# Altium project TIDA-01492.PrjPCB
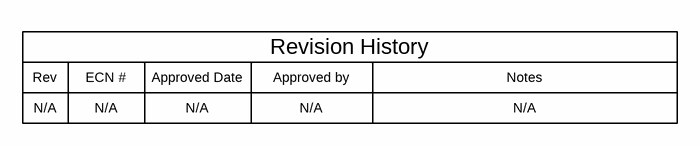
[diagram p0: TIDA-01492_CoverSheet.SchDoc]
CopyrightYear: 2017; EVM_Orderable: N/A; PCB_Layout: Luis Cordova; PCB_Rev: E1; PRJ_Customer: Public Release; PRJ_Engineer: Luis Cordova; PRJ_Number: TIDA-01492; PRJ_Title: Integrated Power Front End and Multi-Phase Processor Supply Reference Design; SCH_Rev: E1; TechSupport: http://www.ti.com/support; TID: TIDA-01492
5 sheets, 142 parts. Net scope: flat (ports and power ports of the same name join across sheets).
Board file: TIDA-01492 Board.PcbDoc
Sheets:
  TIDA-01492_CoverSheet.SchDoc
  Main Supply + Smart Diode.SchDoc
  Core-Voltage Supply.SchDoc
  Memory + IO + CAN Supply.SchDoc
  TIDA-01492_EVM_Hardware.SchDoc

## Sheet TIDA-01492_CoverSheet.SchDoc
size 431 x 279 mm; Date: Not shown in title block; ApprovedBy: Not shown in title block; CheckedBy: Not shown in title block; Author: Not shown in title block; CompanyName: Not shown in title block; Engineer: Not shown in title block; Organization: Not shown in title block; Address1: Not shown in title block; Address2: Not shown in title block; Address3: Not shown in title block; Address4: Not shown in title block; DocumentNumber: 1; Revision: Use project parameter SCH_Rev; SheetNumber: 1; SheetTotal: 5; PageSetup: Record=PageOptions¦CenterHorizontal=True¦CenterVertical=True¦PrintScale=1.00¦XCorrection=1.00¦YCorrection=1.00¦PrintKind=0¦BorderSize=5000000¦LeftOffset=0¦BottomOffset=0¦Orientation=2¦PaperLength=1000¦PaperWidth=1000¦Scale=100¦PaperSource=15¦PrintQuality=600¦MediaType=1¦DitherType=10¦PaperKind=Letter¦PrintScaleMode=1

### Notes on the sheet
- Rev
- N/A
- ECN #
- Approved Date
- Approved by
- Revision History
- Notes

## Sheet Main Supply + Smart Diode.SchDoc
size 431 x 279 mm; Date: Not shown in title block; ApprovedBy: Not shown in title block; CheckedBy: Not shown in title block; Author: Not shown in title block; CompanyName: Not shown in title block; Engineer: Not shown in title block; Organization: Not shown in title block; Address1: Not shown in title block; Address2: Not shown in title block; Address3: Not shown in title block; Address4: Not shown in title block; DocumentNumber: 1; Revision: Use project parameter SCH_Rev; SheetNumber: 2; SheetTotal: 5; PageSetup: Record=PageOptions¦CenterHorizontal=True¦CenterVertical=True¦PrintScale=1.00¦XCorrection=1.00¦YCorrection=1.00¦PrintKind=0¦BorderSize=5000000¦LeftOffset=0¦BottomOffset=0¦Orientation=2¦PaperLength=1000¦PaperWidth=1000¦Scale=100¦PaperSource=15¦PrintQuality=600¦MediaType=1¦DitherType=10¦PaperKind=Letter¦PrintScaleMode=1
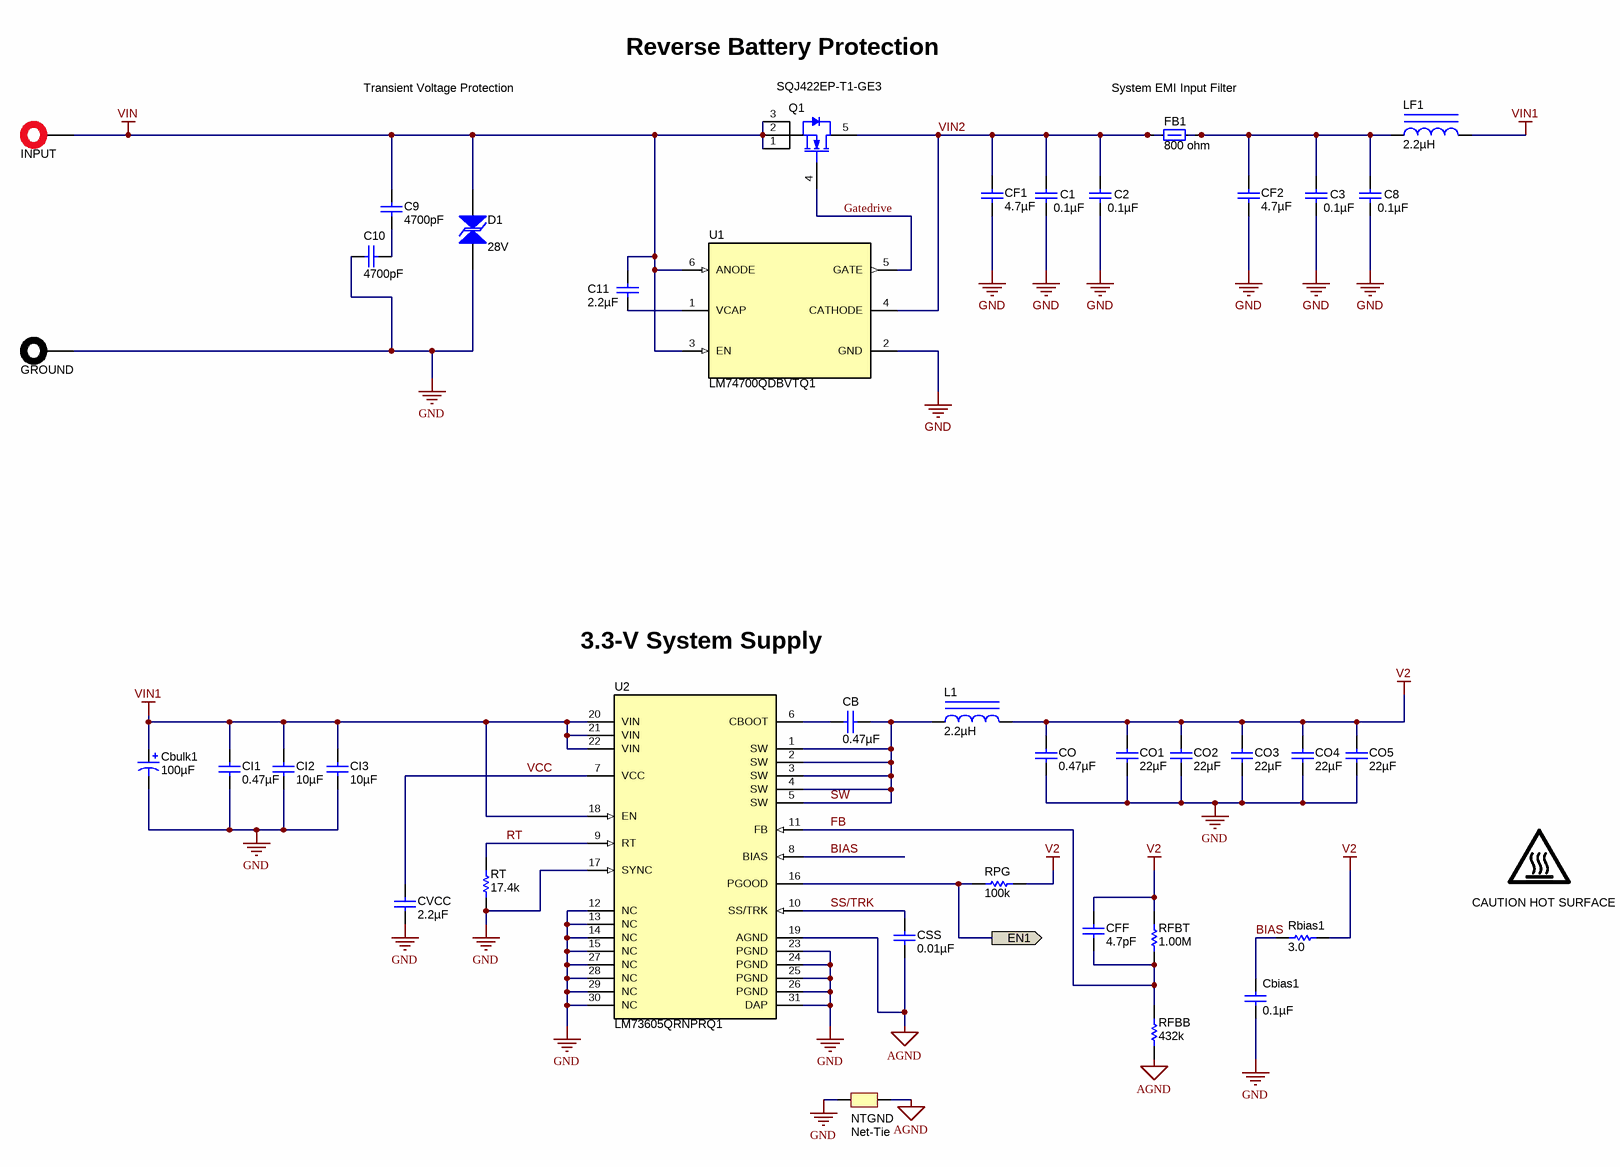
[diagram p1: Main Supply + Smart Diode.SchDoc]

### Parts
C1  ValueDisplayed: 0.1µF  [0603S]  (hidden comment: GCM188R71C104KA37J)
C2  ValueDisplayed: 0.1µF  [0603S]  (hidden comment: GCM188R71C104KA37J)
C3  ValueDisplayed: 0.1µF  [0603S]  (hidden comment: GCM188R71C104KA37J)
C8  ValueDisplayed: 0.1µF  [0603S]  (hidden comment: GCM188R71C104KA37J)
C9  ValueDisplayed: 4700pF  [0603]  (hidden comment: C0603C472J1GAC7867)
C10  ValueDisplayed: 4700pF  [0603]  (hidden comment: C0603C472J1GAC7867)
C11  ValueDisplayed: 2.2µF  [0805_HV]  (hidden comment: C2012X5R1H225K125AB)
CB  ValueDisplayed: 0.47µF  [0603L]  (hidden comment: GRM188R61E474KA12D)
Cbias1  ValueDisplayed: 0.1µF  [0603S]  (hidden comment: GCM188R71C104KA37J)
Cbulk1  ValueDisplayed: 100µF  [HXB_JA0]  (hidden comment: HHXB500ARA101MJA0G)
CF1  ValueDisplayed: 4.7µF  [1210_280]  (hidden comment: CGA6P3X7R1H475M250AB)
CF2  ValueDisplayed: 4.7µF  [1210_280]  (hidden comment: CGA6P3X7R1H475M250AB)
CFF  ValueDisplayed: 4.7pF  [0603]  (hidden comment: 06035A4R7CAT2A)
CI1  ValueDisplayed: 0.47µF  [0603]  (hidden comment: GRM21BR71H474KA88L)
CI2  ValueDisplayed: 10µF  [1210_270]  (hidden comment: GRM32ER71H106KA12L)
CI3  ValueDisplayed: 10µF  [1210_270]  (hidden comment: GRM32ER71H106KA12L)
CO  ValueDisplayed: 0.47µF  [0805_HV]  (hidden comment: GRM21BR71H474KA88L)
CO1  ValueDisplayed: 22µF  [1210_270]  (hidden comment: GRM32ER71C226KE18L)
CO2  ValueDisplayed: 22µF  [1210_270]  (hidden comment: GRM32ER71C226KE18L)
CO3  ValueDisplayed: 22µF  [1210_270]  (hidden comment: GRM32ER71C226KE18L)
CO4  ValueDisplayed: 22µF  [1210_270]  (hidden comment: GRM32ER71C226KE18L)
CO5  ValueDisplayed: 22µF  [1210_270]  (hidden comment: GRM32ER71C226KE18L)
CSS  ValueDisplayed: 0.01µF  [0603]  (hidden comment: 06031C103MAT2A)
CVCC  ValueDisplayed: 2.2µF  [0603]  (hidden comment: GRM188C81A225KE34D)
D1  value 28V  [SMB-Bi]  (hidden comment: SMBJ28CA-13-F)
FB1  ValueDisplayed: 800 ohm  [2220_390]  (hidden comment: HR2220V801R-10)
GND_  GROUND  [6092]
IN  INPUT  [6091]
L1  ValueDisplayed: 2.2µH  [XAL7030]  (hidden comment: XAL7030-222MEB)
LF1  ValueDisplayed: 2.2µH  [XAL5030]  (hidden comment: XAL5030-222MEB)
LOGO4  CAUTION HOT SURFACE  [IEC_HotSurface_Small]  (no BOM)
NTGND  Net-Tie  [Net-Tie_20milWide_60milLong]  (net tie, no BOM)
Q1  SQJ422EP-T1-GE3  [PowerPAK_SO-8L]
Rbias1  ValueDisplayed: 3.0  [0402S]  (hidden comment: CRCW04023R00JNED)
RFBB  ValueDisplayed: 432k  [0603]  (hidden comment: CRCW0603432KFKEA)
RFBT  ValueDisplayed: 1.00M  [0603]  (hidden comment: CRCW06031M00FKEA)
RPG  ValueDisplayed: 100k  [0603]  (hidden comment: CRCW0603100KFKEA)
RT  ValueDisplayed: 17.4k  [0603]  (hidden comment: CRCW060317K4FKEA)
U1  LM74700QDBVTQ1  [DDC0006A_N]
U2  LM73605QRNPRQ1  [RNP0030A]

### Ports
EN1 (out)

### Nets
AGND: CSS.2 NTGND.2 RFBB.1 U2.19(AGND)
GND: C1.2 C2.2 C3.2 C8.2 C10.1 Cbias1.2 Cbulk1.2(-) CF1.2 CF2.2 CI1.1 CI2.1 CI3.1 CO.1 CO1.2 CO2.2 CO3.2 CO4.2 CO5.2 CVCC.2 D1.2 GND_.1 NTGND.1 RT.2 U1.2(GND) U2.12(NC) U2.13(NC) U2.14(NC) U2.15(NC) U2.17(SYNC) U2.23(PGND) U2.24(PGND) U2.25(PGND) U2.26(PGND) U2.27(NC) U2.28(NC) U2.29(NC) U2.30(NC) U2.31(DAP)
V2: CFF.1 CO.2 CO1.1 CO2.1 CO3.1 CO4.1 CO5.1 L1.2 Rbias1.2 RFBT.2 RPG.2
VIN: C9.1 C11.1 D1.1 IN.1 Q1.1(S) Q1.2(S) Q1.3(S) U1.3(EN) U1.6(ANODE)
VIN1: Cbulk1.1(+) CI1.2 CI2.2 CI3.2 LF1.2 U2.18(EN) U2.20(VIN) U2.21(VIN) U2.22(VIN)
BIAS: Cbias1.1 Rbias1.1 U2.8(BIAS)
FB: CFF.2 RFBB.2 RFBT.1 U2.11(FB)
Gatedrive: Q1.4(G) U1.5(GATE)
RT: RT.1 U2.9(RT)
SS/TRK: CSS.1 U2.10(SS/TRK)
SW: CB.2 L1.1 U2.1(SW) U2.2(SW) U2.3(SW) U2.4(SW) U2.5(SW)
VCC: CVCC.1 U2.7(VCC)
VIN2: C1.1 C2.1 CF1.1 FB1.1 Q1.5(D) U1.4(CATHODE)
NetC3_1: C3.1 C8.1 CF2.1 FB1.2 LF1.1
NetC9_2: C9.2 C10.2
NetC11_2: C11.2 U1.1(VCAP)
NetCB_1: CB.1 U2.6(CBOOT)
NetRPG_1: RPG.1 U2.16(PGOOD) ; port EN1

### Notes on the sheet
- Reverse Battery Protection
- Transient Voltage Protection
- (near FB1) System EMI Input Filter
- 3.3-V System Supply

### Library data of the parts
C1-C3 C8 = GCM188R71C104KA37J: CAP, CERM, 0.1 µF, 16 V, +/- 10%, X7R, AEC-Q200 Grade 1, 0603; Manufacturer: MuRata; Polarized: N; CompType: Capacitor; Value: 0.1uF; U/M: EA; Cap_F: 0.0000001; Tolerance_%: 10; Value1: Unknown; VDC_V: 16; Value2: 16V; TaMin_C: -55; TaMax_C: 125; Cap_Case: 0603; AEC Category: Q200; AEC Qualified: Y; AEC Grade: 1; SizeArea_mm2: 1.28; SizeAreaWB_mm2: 4.68; SizeX_mm: 1.6; SizeY_mm: 0.8
C9 C10 = C0603C472J1GAC7867: CAP, CERM, 4700 pF, 100 V, +/- 5%, C0G/NP0, 0603; Manufacturer: Kemet; Polarized: N; CompType: Capacitor; Value: 4700pF; U/M: EA; Cap_F: 0.0000000047; Tolerance_%: 5; Value1: Unknown; VDC_V: 100; Value2: 100V; TaMin_C: -55; TaMax_C: 125; SizeArea_mm2: 1.28; SizeAreaWB_mm2: 4.68; SizeX_mm: 1.6; SizeY_mm: 0.8; SizeZ_mm: 1; AEC Category: Q200
C11 = C2012X5R1H225K125AB: CAP, CERM, 2.2 µF, 50 V, +/- 10%, X5R, 0805; Manufacturer: TDK; CompType: Capacitor; Value: 2.2uF; Polarized: N; U/M: EA; Cap_F: 0.0000022; Tolerance_%: 10; Value1: Unknown; VDC_V: 50; Value2: 50V; TaMin_C: -55; TaMax_C: 85; Cap_Case: 0805
CB = GRM188R61E474KA12D: CAP, CERM, 0.47uF, 25V, +/-10%, X5R, 0603; Manufacturer: MuRata; Polarized: N; CompType: Capacitor; U/M: EA; Cap_F: 0.00000047; Tolerance_%: 10; Value1: Unknown; VDC_V: 25; TaMin_C: -55; TaMax_C: 85; Cap_Case: 0603
Cbias1 = GCM188R71C104KA37J: CAP, CERM, 0.1 µF, 16 V, +/- 10%, X7R, AEC-Q200 Grade 1, 0603; Manufacturer: MuRata; Polarized: N; CompType: Capacitor; Value: 0.1uF; U/M: EA; Cap_F: 0.0000001; Tolerance_%: 10; Value1: Unknown; VDC_V: 16; Value2: 16V; TaMin_C: -55; TaMax_C: 125; Cap_Case: 0603; AEC Category: Q200; AEC Qualified: Y; AEC Grade: 1
Cbulk1 = HHXB500ARA101MJA0G: CAP, Aluminum Polymer, 100 µF, 50 V, +/- 20%, 0.025 ohm, AEC-Q200 Grade 2, D10xL10mm SMD; Manufacturer: Chemi-Con; Polarized: Y; CompType: Capacitor; Value: 100uF; U/M: EA; Cap_F: 0.0001; Tolerance_%: 20; VDC_V: 50; Value2: 50V; ESR_ohm: 0.025; IRMS_A: 2; TaMin_C: -55; TaMax_C: 105; Cap_Case: 10x10mm; AEC Category: Q200
CF1 CF2 = CGA6P3X7R1H475M250AB: CAP, CERM, 4.7 µF, 50 V, +/- 20%, X7R, AEC-Q200 Grade 1, 1210; Manufacturer: TDK; Polarized: N; CompType: Capacitor; Value: 4.7uF; U/M: EA; Cap_F: 0.0000047; Tolerance_%: 20; Value1: Unknown; VDC_V: 50; Value2: 50V; TaMin_C: -55; TaMax_C: 125; Cap_Case: 1210; AEC Category: Q200; AEC Qualified: Y; AEC Grade: 1
CFF = 06035A4R7CAT2A: CAP, CERM, 4.7 pF, 50 V, +/- 5%, C0G/NP0, 0603; Manufacturer: AVX; Polarized: N; CompType: Capacitor; Value: 4.7pF; U/M: EA; Cap_F: 0.0000000000047; Tolerance_%: 5; ESR_ohm: 0.633; Value1: 0.633 ohm; VDC_V: 50; Value2: 50V; TaMin_C: -55; TaMax_C: 125; AEC Category: Q200
CI1 = GRM21BR71H474KA88L: CAP, CERM, 0.47 µF, 50 V, +/- 10%, X7R, 0805; Manufacturer: MuRata; Polarized: N; CompType: Capacitor; Value: 0.47uF; U/M: EA; Cap_F: 0.00000047; Tolerance_%: 10; Value1: Unknown; VDC_V: 50; Value2: 50V; TaMin_C: -55; TaMax_C: 125; Cap_Case: 0805; SizeArea_mm2: 2.5; SizeAreaWB_mm2: 6.75; SizeX_mm: 2; SizeY_mm: 1.25; SizeZ_mm: 1.45; AEC Category: Q200
CI2 CI3 = GRM32ER71H106KA12L: CAP, CERM, 10 µF, 50 V, +/- 10%, X7R, 1210; Manufacturer: MuRata; Polarized: N; CompType: Capacitor; Value: 10uF; U/M: EA; Cap_F: 0.00001; Tolerance_%: 10; Value1: Unknown; VDC_V: 50; Value2: 50V; TaMin_C: -55; TaMax_C: 125; Cap_Case: 1210; SizeArea_mm2: 8; SizeAreaWB_mm2: 14.7; SizeX_mm: 3.2; SizeY_mm: 2.5; SizeZ_mm: 2.7; AEC Category: Q200
CO = GRM21BR71H474KA88L: CAP, CERM, 0.47 µF, 50 V, +/- 10%, X7R, 0805; Manufacturer: MuRata; Polarized: N; CompType: Capacitor; Value: 0.47uF; U/M: EA; Cap_F: 0.00000047; Tolerance_%: 10; Value1: Unknown; VDC_V: 50; Value2: 50V; TaMin_C: -55; TaMax_C: 125; Cap_Case: 0805
CO1-CO5 = GRM32ER71C226KE18L: CAP, CERM, 22 µF, 16 V, +/- 10%, X7R, 1210; Manufacturer: MuRata; Polarized: N; CompType: Capacitor; Value: 22uF; U/M: EA; Cap_F: 0.000022; Tolerance_%: 10; ESR_ohm: 0.003; Value1: 0.003 ohm; VDC_V: 16; Value2: 16V; TaMin_C: -55; TaMax_C: 125; Cap_Case: 1210; AEC Category: Q200; SizeArea_mm2: 8; SizeAreaWB_mm2: 14.7; SizeX_mm: 3.2; SizeY_mm: 2.5; SizeZ_mm: 2.7
CSS = 06031C103MAT2A: CAP, CERM, 0.01 µF, 100 V, +/- 20%, X7R, 0603; Manufacturer: AVX; Polarized: N; CompType: Capacitor; Value: 0.01uF; U/M: EA; Cap_F: 0.00000001; Tolerance_%: 20; ESR_ohm: 0.098; Value1: 0.098 ohm; VDC_V: 100; Value2: 100V; TaMin_C: -55; TaMax_C: 125
CVCC = GRM188C81A225KE34D: CAP, CERM, 2.2uF, 10V, +/-10%, X6S, 0603; Manufacturer: MuRata; Polarized: N; CompType: Capacitor; U/M: EA; Cap_F: 0.0000022; Tolerance_%: 10; Value1: Unknown; TaMin_C: -55; TaMax_C: 105
D1 = SMBJ28CA-13-F: Diode, TVS, Bi, 28 V, 45.4 Vc, SMB; Manufacturer: Diodes Inc.; U/M: EA; Power_W: 5; Vr_V: 28; Value1: 5W; AEC Category: Q101; AEC Qualified: N
FB1 = HR2220V801R-10: Ferrite Bead, 800 ohm @ 100 MHz, 8 A, 2220; Manufacturer: Laird-Signal Integrity Products; Value: 800 ohm; Imax_A: 8; DCR_ohm: 0.01; Value1: 0.01 ohm; Value2: 8A; ZTyp@100MHz_Ohm: 800; Ztyp@1GHz_Ohm: 75; SizeAreaWB_mm2: 53.96; SizeArea_mm2: 28.56; SizeX_mm: 5.6; SizeY_mm: 5.1; SizeZ_mm: 3.9
GND_ = 6092: Standard Banana Jack, Insulated, Black; Manufacturer: Keystone; SymbolCreator: a0412235; CompType: Connector; U/M: EA
IN = 6091: Standard Banana Jack, Insulated, Red; Manufacturer: Keystone; SymbolCreator: a0412235; CompType: Connector; U/M: EA
L1 = XAL7030-222MEB: Inductor, Shielded, Composite, 2.2 µH, 12.9 A, 0.0137 ohm, SMD; Manufacturer: Coilcraft; Value: 2.2uH; Ind_H: 2.2E-6; Imax_A: 12.9; Irms: 12.9A @ 40C rise; Isat: 18A @ 0.7% inductance drop; DCR_ohm: 0.0137; Value2: 12.9A; AEC Category: Q200; SizeAreaWB_mm2: 100; SizeArea_mm2: 64; SizeX_mm: 8; SizeZ_mm: 3.1
LF1 = XAL5030-222MEB: Inductor, Shielded, Composite, 2.2 µH, 9.2 A, 0.01 ohm, SMD; Manufacturer: Coilcraft; Value: 2.2uH; Ind_H: 2.2E-6; Imax_A: 9.2; Irms: 9.2A @ 40C rise; Isat: 12.9A @ 30% inductance drop; DCR_ohm: 0.01; Value2: 9.2A; AEC Category: Q200; SizeAreaWB_mm2: 54.4544; SizeArea_mm2: 28.9344; SizeX_mm: 5.28; SizeY_mm: 5.48; SizeZ_mm: 3.1
LOGO4 = IEC_HotSurface: IEC 61010-1 Hot Surface Warning; SymbolCreator: a0412235
NTGND = Net-Tie: Single point connection between nets.; SymbolCreator: codlsc
Q1 = SQJ422EP-T1-GE3: MOSFET, N-CH, 40 V, 75 A, PowerPAK_SO-8L; Manufacturer: Vishay-Siliconix; Alternate Manufacturer: None; U/M: EA; ChType: N; Value: 40V; VdsMax_V: 40; Value1: 0.0043 ohm; Rdson45_ohm: 0.0043; Value2: 67 nC; QgTyp_nC: 67; Vgs_V: 20; IdsMax_A: 75; SymbolCreator: a0412235
Rbias1 = CRCW04023R00JNED: RES, 3.0, 5%, 0.063 W, 0402; Manufacturer: Vishay-Dale; CompType: Resistor; Value: 3.0; Res_ohm: 3; Value_Code: 3R00; Tolerance_%: 5; Power_W: 0.063; Value2: 0.063W; VDC_V: 50; TempCo: 200 ppm/C; EIA_Code: E24; U/M: EA; AEC Category: Q200
RFBB = CRCW0603432KFKEA: RES, 432 k, 1%, 0.1 W, 0603; Manufacturer: Vishay-Dale; CompType: Resistor; Value: 432k; Res_ohm: 432000; Tolerance_%: 1; Power_W: 0.1; Value2: 0.1W; VDC_V: 75; TempCo: 100 ppm/C; EIA_Code: E96; U/M: EA; AEC Category: Q200; SizeArea_mm2: 1.28; SizeX_mm: 1.6; SizeY_mm: 0.8; Green_Lifecycle: Active; Green_REACh: Passed
RFBT = CRCW06031M00FKEA: RES, 1.00 M, 1%, 0.1 W, 0603; Manufacturer: Vishay-Dale; CompType: Resistor; Value: 1.00Meg; Res_ohm: 1000000; Value_Code: 1M00; Tolerance_%: 1; Power_W: 0.1; Value2: 0.1W; VDC_V: 75; TempCo: 100 ppm/C; EIA_Code: E96; U/M: EA; AEC Category: Q200
RPG = CRCW0603100KFKEA: RES, 100 k, 1%, 0.1 W, 0603; Manufacturer: Vishay-Dale; CompType: Resistor; Value: 100k; Res_ohm: 100000; Tolerance_%: 1; Power_W: 0.1; Value2: 0.1W; VDC_V: 75; TempCo: 100 ppm/C; EIA_Code: E96; U/M: EA
RT = CRCW060317K4FKEA: RES, 17.4 k, 1%, 0.1 W, 0603; Manufacturer: Vishay-Dale; CompType: Resistor; Value: 17.4k; Res_ohm: 17400; Value_Code: 17k4; Tolerance_%: 1; Power_W: 0.1; Value2: 0.1W; VDC_V: 75; TempCo: 100 ppm/C; EIA_Code: E96; U/M: EA
U1 = LM74700QDDCRQ1: Low Iq Always ON Smart Diode Controller, DDC0006A (SOT-6); Manufacturer: Texas Instruments; SymbolCreator: Altium; SizeArea_mm2: 4.8675; SizeAreaWB_mm2: 10.4675; SizeX_mm: 1.65; SizeY_mm: 2.95; SizeZ_mm: 0.87; CompType: IC; U/M: EA
U2 = LM73605QRNPRQ1: 3.5V to 36V 5A Synchronous Step-Down Voltage Regulator, RNP0030A (WQFN-30); Alternate PartNumber: LM73605QRNPTQ1; Manufacturer: Texas Instruments; SymbolCreator: a0411947; SizeArea_mm2: 24; SizeAreaWB_mm2: 48; SizeX_mm: 4; SizeY_mm: 6; SizeZ_mm: 0.8; CompType: IC; U/M: EA

## Sheet Core-Voltage Supply.SchDoc
size 431 x 279 mm; Date: Not shown in title block; ApprovedBy: Not shown in title block; CheckedBy: Not shown in title block; Author: Not shown in title block; CompanyName: Not shown in title block; Engineer: Not shown in title block; Organization: Not shown in title block; Address1: Not shown in title block; Address2: Not shown in title block; Address3: Not shown in title block; Address4: Not shown in title block; DocumentNumber: 1; Revision: Use project parameter SCH_Rev; SheetNumber: 3; SheetTotal: 5; PageSetup: Record=PageOptions¦CenterHorizontal=True¦CenterVertical=True¦PrintScale=1.00¦XCorrection=1.00¦YCorrection=1.00¦PrintKind=0¦BorderSize=5000000¦LeftOffset=0¦BottomOffset=0¦Orientation=2¦PaperLength=1000¦PaperWidth=1000¦Scale=100¦PaperSource=15¦PrintQuality=600¦MediaType=1¦DitherType=10¦PaperKind=Letter¦PrintScaleMode=1
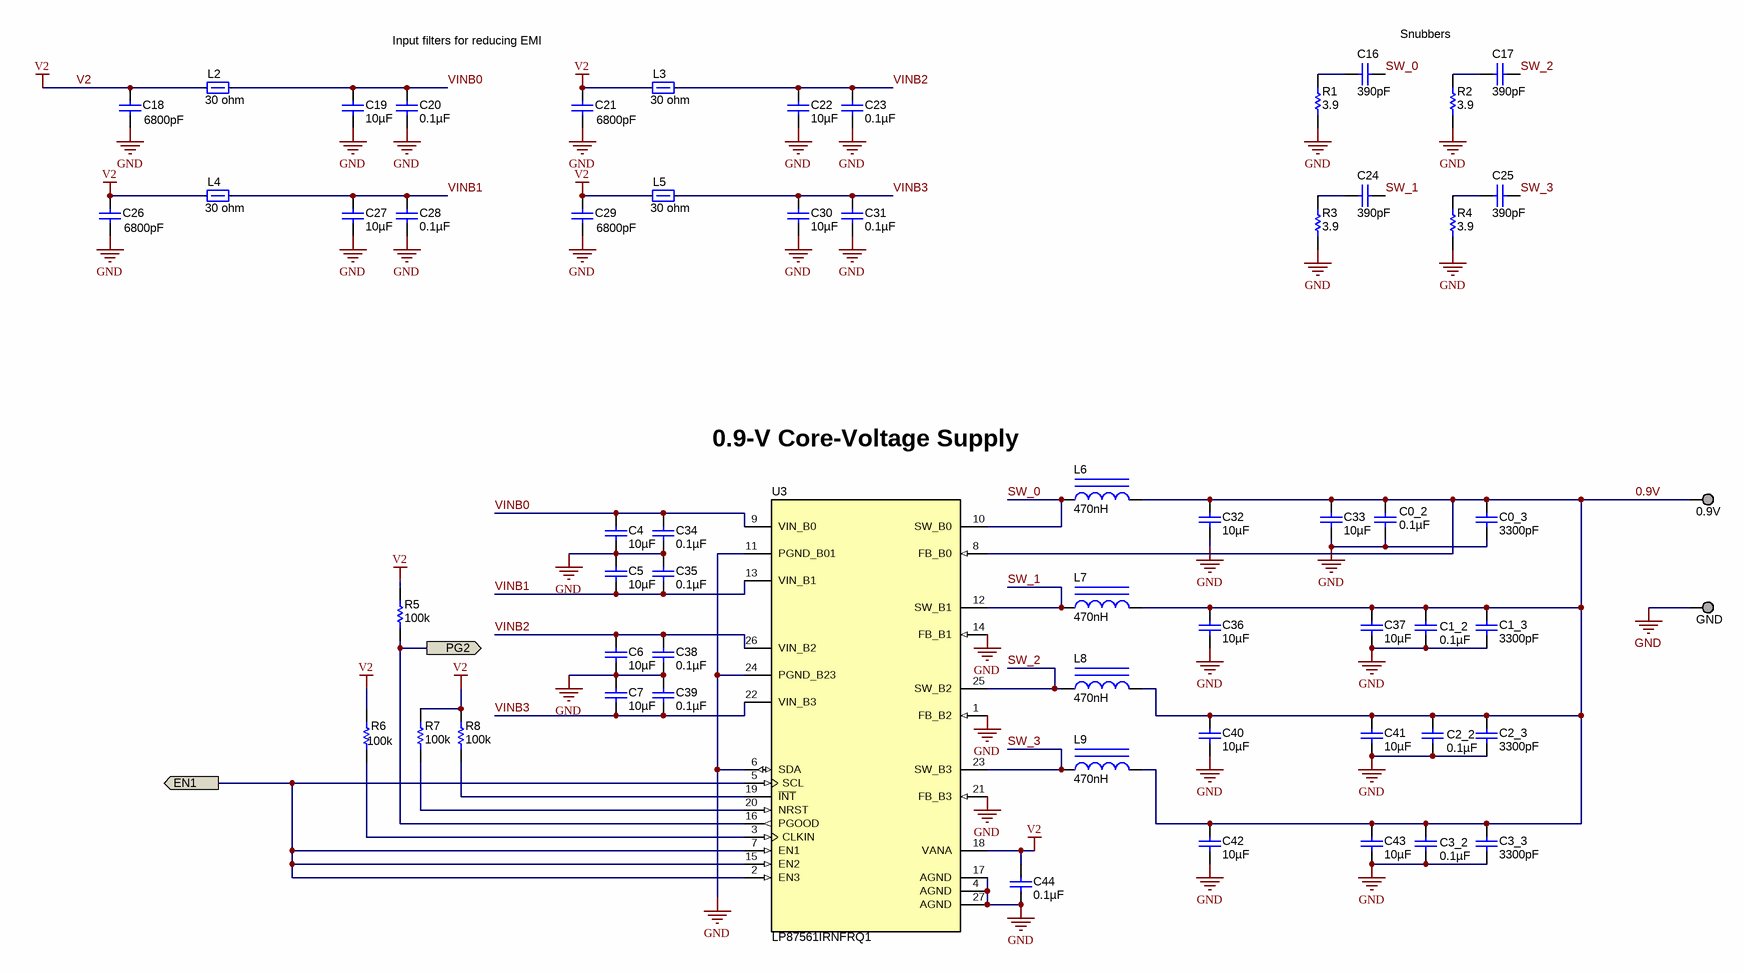
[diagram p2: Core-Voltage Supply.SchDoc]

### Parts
0.9V  0.9V  [Keystone1503-2]
C0_2  ValueDisplayed: 0.1µF  [0603]  (hidden comment: GRM188R71C104KA01D)
C0_3  ValueDisplayed: 3300pF  [0402L]  (hidden comment: GRM155R71H332KA01D)
C1_2  ValueDisplayed: 0.1µF  [0603]  (hidden comment: GRM188R71C104KA01D)
C1_3  ValueDisplayed: 3300pF  [0402L]  (hidden comment: GRM155R71H332KA01D)
C2_2  ValueDisplayed: 0.1µF  [0603]  (hidden comment: GRM188R71C104KA01D)
C2_3  ValueDisplayed: 3300pF  [0402L]  (hidden comment: GRM155R71H332KA01D)
C3_2  ValueDisplayed: 0.1µF  [0603]  (hidden comment: GRM188R71C104KA01D)
C3_3  ValueDisplayed: 3300pF  [0402L]  (hidden comment: GRM155R71H332KA01D)
C4  ValueDisplayed: 10µF  [0805L]  (hidden comment: GCM21BR71A106KE22L)
C5  ValueDisplayed: 10µF  [0805L]  (hidden comment: GCM21BR71A106KE22L)
C6  ValueDisplayed: 10µF  [0805L]  (hidden comment: GCM21BR71A106KE22L)
C7  ValueDisplayed: 10µF  [0805L]  (hidden comment: GCM21BR71A106KE22L)
C16  ValueDisplayed: 390pF  [0402L]  (hidden comment: GRM155R71H391KA01D)
C17  ValueDisplayed: 390pF  [0402L]  (hidden comment: GRM155R71H391KA01D)
C18  ValueDisplayed: 6800pF  [0402L]  (hidden comment: GRM155R71H682KA88D)
C19  ValueDisplayed: 10µF  [0805_HV]  (hidden comment: GRM21BR60J106KE19L)
C20  ValueDisplayed: 0.1µF  [0402L]  (hidden comment: GRM155R71C104JA88D)
C21  ValueDisplayed: 6800pF  [0402L]  (hidden comment: GRM155R71H682KA88D)
C22  ValueDisplayed: 10µF  [0805_HV]  (hidden comment: GRM21BR60J106KE19L)
C23  ValueDisplayed: 0.1µF  [0402L]  (hidden comment: GRM155R71C104JA88D)
C24  ValueDisplayed: 390pF  [0402L]  (hidden comment: GRM155R71H391KA01D)
C25  ValueDisplayed: 390pF  [0402L]  (hidden comment: GRM155R71H391KA01D)
C26  ValueDisplayed: 6800pF  [0402L]  (hidden comment: GRM155R71H682KA88D)
C27  ValueDisplayed: 10µF  [0805_HV]  (hidden comment: GRM21BR60J106KE19L)
C28  ValueDisplayed: 0.1µF  [0402L]  (hidden comment: GRM155R71C104JA88D)
C29  ValueDisplayed: 6800pF  [0402L]  (hidden comment: GRM155R71H682KA88D)
C30  ValueDisplayed: 10µF  [0805L]  (hidden comment: GRM21BR60J106KE19L)
C31  ValueDisplayed: 0.1µF  [0402L]  (hidden comment: GRM155R71C104JA88D)
C32  ValueDisplayed: 10µF  [1206_180]  (hidden comment: GCM31CR71A106KA64L)
C33  ValueDisplayed: 10µF  [1206_180]  (hidden comment: GCM31CR71A106KA64L)
C34  ValueDisplayed: 0.1µF  [0402L]  (hidden comment: GRM155R71C104JA88D)
C35  ValueDisplayed: 0.1µF  [0402L]  (hidden comment: GRM155R71C104JA88D)
C36  ValueDisplayed: 10µF  [1206_180]  (hidden comment: GCM31CR71A106KA64L)
C37  ValueDisplayed: 10µF  [1206_180]  (hidden comment: GCM31CR71A106KA64L)
C38  ValueDisplayed: 0.1µF  [0402L]  (hidden comment: GRM155R71C104JA88D)
C39  ValueDisplayed: 0.1µF  [0402L]  (hidden comment: GRM155R71C104JA88D)
C40  ValueDisplayed: 10µF  [1206_180]  (hidden comment: GCM31CR71A106KA64L)
C41  ValueDisplayed: 10µF  [1206_180]  (hidden comment: GCM31CR71A106KA64L)
C42  ValueDisplayed: 10µF  [1206_180]  (hidden comment: GCM31CR71A106KA64L)
C43  ValueDisplayed: 10µF  [1206_180]  (hidden comment: GCM31CR71A106KA64L)
C44  ValueDisplayed: 0.1µF  [0402L]  (hidden comment: GRM155R71C104JA88D)
GND1  GND  [Keystone1503-2]
L2  value 30 ohm  [0805_HV1]  (hidden comment: BLM21PG300SH1D)
L3  value 30 ohm  [0805_HV1]  (hidden comment: BLM21PG300SH1D)
L4  value 30 ohm  [0805_HV1]  (hidden comment: BLM21PG300SH1D)
L5  value 30 ohm  [0805_HV1]  (hidden comment: BLM21PG300SH1D)
L6  ValueDisplayed: 470nH  [DFE252012C]  (hidden comment: DFE252012F-R47M=P2)
L7  ValueDisplayed: 470nH  [DFE252012C]  (hidden comment: DFE252012F-R47M=P2)
L8  ValueDisplayed: 470nH  [DFE252012C]  (hidden comment: DFE252012F-R47M=P2)
L9  ValueDisplayed: 470nH  [DFE252012C]  (hidden comment: DFE252012F-R47M=P2)
R1  ValueDisplayed: 3.9  [0805_HV]  (hidden comment: CRCW08053R90JNEA)
R2  ValueDisplayed: 3.9  [0805_HV]  (hidden comment: CRCW08053R90JNEA)
R3  ValueDisplayed: 3.9  [0805_HV]  (hidden comment: CRCW08053R90JNEA)
R4  ValueDisplayed: 3.9  [0805_HV]  (hidden comment: CRCW08053R90JNEA)
R5  ValueDisplayed: 100k  [0402L]  (hidden comment: CRCW0402100KFKED)
R6  ValueDisplayed: 100k  [0402]  (hidden comment: CRCW0402100KFKED)
R7  ValueDisplayed: 100k  [0402L]  (hidden comment: CRCW0402100KFKED)
R8  ValueDisplayed: 100k  [0402L]  (hidden comment: CRCW0402100KFKED)
U3  LP87561IRNFRQ1  [RNF0026C]

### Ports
EN1 (out), PG2 (out)

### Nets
GND: C0_2.1 C0_3.2 C1_2.1 C1_3.2 C2_2.1 C2_3.2 C3_2.1 C3_3.2 C4.2 C5.1 C6.2 C7.1 C18.2 C19.2 C20.1 C21.2 C22.2 C23.1 C26.2 C27.2 C28.1 C29.2 C30.2 C31.1 C32.2 C33.2 C34.1 C35.2 C36.2 C37.2 C38.1 C39.2 C40.2 C41.2 C42.2 C43.2 C44.2 GND1.1 R1.1 R2.1 R3.1 R4.1 U3.1(FB_B2) U3.4(AGND) U3.6(SDA) U3.11(PGND_B01) U3.14(FB_B1) U3.17(AGND) U3.21(FB_B3) U3.24(PGND_B23) U3.27(AGND)
V2: C18.1 C21.1 C26.1 C29.1 C44.1 L2.1 L3.1 L4.1 L5.1 R5.1 R6.1 R7.1 R8.1 U3.18(VANA)
0.9V: 0.9V.1 C0_2.2 C0_3.1 C1_2.2 C1_3.1 C2_2.2 C2_3.1 C3_2.2 C3_3.1 C32.1 C33.1 C36.1 C37.1 C40.1 C41.1 C42.1 C43.1 L6.2 L7.2 L8.2 L9.2 U3.8(FB_B0)
SW_0: C16.1 L6.1 U3.10(SW_B0)
SW_1: C24.1 L7.1 U3.12(SW_B1)
SW_2: C17.1 L8.1 U3.25(SW_B2)
SW_3: C25.1 L9.1 U3.23(SW_B3)
VINB0: C4.1 C19.1 C20.2 C34.2 L2.2 U3.9(VIN_B0)
VINB1: C5.2 C27.1 C28.2 C35.1 L4.2 U3.13(VIN_B1)
VINB2: C6.1 C22.1 C23.2 C38.2 L3.2 U3.26(VIN_B2)
VINB3: C7.2 C30.1 C31.2 C39.1 L5.2 U3.22(VIN_B3)
NetC16_2: C16.2 R1.2
NetC17_2: C17.2 R2.2
NetC24_2: C24.2 R3.2
NetC25_2: C25.2 R4.2
NetR5_2: R5.2 U3.16(PGOOD) ; port PG2
NetR6_2: R6.2 U3.3(CLKIN)
NetR7_2: R7.2 U3.20(NRST)
NetR8_2: R8.2 U3.19(~{INT})
NetRPG_1: U3.2(EN3) U3.5(SCL) U3.7(EN1) U3.15(EN2) ; port EN1

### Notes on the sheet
- Input filters for reducing EMI
- Snubbers
- 0.9-V Core-Voltage Supply

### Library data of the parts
0.9V GND1 = 1503-2: Terminal, Turret, TH, Double; Manufacturer: Keystone; CompType: Turret Terminal; U/M: EA
C0_2 C1_2 C2_2 C3_2 = GRM188R71C104KA01D: CAP, CERM, 0.1 µF, 16 V, +/- 10%, X7R, 0603; Manufacturer: MuRata; Alternate PartNumber: GRM155R71E104ME14D; Polarized: N; CompType: Capacitor; Value: 0.1uF; U/M: EA; Cap_F: 0.0000001; Tolerance_%: 10; Value1: Unknown; VDC_V: 16; Value2: 16V; TaMin_C: -55; TaMax_C: 125; AEC Category: Q200; SizeArea_mm2: 1.28; SizeAreaWB_mm2: 4.68; SizeX_mm: 1.6; SizeY_mm: 0.8; SizeZ_mm: 1
C0_3 C1_3 C2_3 C3_3 = GRM155R71H332KA01D: CAP, CERM, 3300 pF, 50 V, +/- 10%, X7R, 0402; Manufacturer: MuRata; Polarized: N; CompType: Capacitor; Value: 3300pF; U/M: EA; Cap_F: 0.0000000033; Tolerance_%: 10; Value1: Unknown; VDC_V: 50; Value2: 50V; TaMin_C: -55; TaMax_C: 125; Cap_Case: 0402; SizeArea_mm2: 0.5; SizeAreaWB_mm2: 3; SizeX_mm: 1; SizeZ_mm: 0.6; AEC Category: Q200
C4-C7 = GCM21BR71A106KE22L: CAP, CERM, 10 µF, 10 V, +/- 10%, X7R, 0805; Manufacturer: MuRata; Polarized: N; CompType: Capacitor; Value: 10uF; U/M: EA; Cap_F: 0.00001; Tolerance_%: 10; Value1: Unknown; Value2: 10V; TaMin_C: -55; TaMax_C: 125; Cap_Case: 0805; SizeArea_mm2: 2.5; SizeAreaWB_mm2: 6.75; SizeX_mm: 2; SizeY_mm: 1.25; SizeZ_mm: 1.45; AEC Category: Q200
C16 C17 C24 C25 = GRM155R71H391KA01D: CAP, CERM, 390 pF, 50 V, +/- 10%, X7R, 0402; Manufacturer: MuRata; Polarized: N; CompType: Capacitor; Value: 390pF; U/M: EA; Cap_F: 0.00000000039; Tolerance_%: 10; Value1: Unknown; VDC_V: 50; Value2: 50V; TaMin_C: -55; TaMax_C: 125; Cap_Case: 0402; SizeArea_mm2: 0.5; SizeAreaWB_mm2: 3; SizeX_mm: 1; SizeZ_mm: 0.6; AEC Category: Q200
C18 C21 C26 C29 = GRM155R71H682KA88D: CAP, CERM, 6800 pF, 50 V, +/- 10%, X7R, 0402; Manufacturer: MuRata; Polarized: N; CompType: Capacitor; Value: 6800pF; U/M: EA; Cap_F: 0.0000000068; Tolerance_%: 10; Value1: Unknown; VDC_V: 50; Value2: 50V; TaMin_C: -55; TaMax_C: 125; Cap_Case: 0402; AEC Category: Q200; SizeArea_mm2: 0.5; SizeAreaWB_mm2: 3; SizeX_mm: 1; SizeZ_mm: 0.6
C19 C22 C27 C30 = GRM21BR60J106KE19L: CAP, CERM, 10 µF, 6.3 V, +/- 10%, X5R, 0805; Manufacturer: MuRata; Polarized: N; CompType: Capacitor; Value: 10uF; U/M: EA; Cap_F: 0.00001; Tolerance_%: 10; ESR_ohm: 0.003; Value1: 0.003 ohm; VDC_V: 6.3; Value2: 6.3V; TaMin_C: -55; TaMax_C: 85; Cap_Case: 0805; AEC Category: Q200; SizeArea_mm2: 2.5; SizeAreaWB_mm2: 6.75; SizeX_mm: 2; SizeY_mm: 1.25; SizeZ_mm: 1.45
C20 C23 C28 C31 C34 C35 C38 C39 C44 = GRM155R71C104JA88D: CAP, CERM, 0.1 µF, 16 V, +/- 5%, X7R, 0402; Manufacturer: MuRata; Polarized: N; CompType: Capacitor; Value: 0.1uF; U/M: EA; Cap_F: 0.0000001; Tolerance_%: 5; Value1: Unknown; VDC_V: 16; Value2: 16V; TaMin_C: -55; TaMax_C: 125; Cap_Case: 0402; SizeArea_mm2: 0.5; SizeAreaWB_mm2: 3; SizeX_mm: 1; SizeZ_mm: 0.6; AEC Category: Q200
C32 C33 C36 C37 C40-C43 = GCM31CR71A106KA64L: CAP, CERM, 10 µF, 10 V, +/- 10%, X7R, AEC-Q200 Grade 1, 1206; Manufacturer: MuRata; Polarized: N; CompType: Capacitor; Value: 10uF; U/M: EA; Cap_F: 0.00001; Tolerance_%: 10; Value1: Unknown; Value2: 10V; TaMin_C: -55; TaMax_C: 125; Cap_Case: 1206; SizeArea_mm2: 5.12; SizeAreaWB_mm2: 10.92; SizeX_mm: 3.2; SizeY_mm: 1.6; SizeZ_mm: 1.8; AEC Category: Q200; AEC Qualified: Y; AEC Grade: 1
L2-L5 = BLM21PG300SH1D: Ferrite Bead, 30 ohm @ 100 MHz, 4 A, 0805; Manufacturer: MuRata; Imax_A: 4; DCR_ohm: 0.014; Value1: 0.014 ohm; Value2: 4A; ZTyp@100MHz_Ohm: 30
L6-L9 = DFE252012F-R47M=P2: Inductor, Powdered Iron, 470 nH, 5.8 A, 0.017 ohm, SMD; Manufacturer: MuRata Toko; Value: 470nH; Ind_H: 470.0E-9; Imax_A: 5.8; Irms: 5.8A @ 40C rise; Isat: 7.4A @ 30% inductance drop; DCR_ohm: 0.017; Value2: 5.8A; SizeAreaWB_mm2: 11.84; SizeArea_mm2: 5.94; SizeX_mm: 2.7; SizeY_mm: 2.2; SizeZ_mm: 1.2; AEC Category: Q200; AEC Qualified: N
R1-R4 = CRCW08053R90JNEA: RES, 3.9, 5%, 0.125 W, 0805; Manufacturer: Vishay-Dale; CompType: Resistor; Value: 3.9; Value_Code: 3R90; Tolerance_%: 5; Power_W: 0.125; Value2: 0.125W; VDC_V: 150; TempCo: 200 ppm/C; SizeArea_mm2: 2.5; SizeX_mm: 2; SizeY_mm: 1.25; SizeZ_mm: 1.45; EIA_Code: E24; U/M: EA; AEC Category: Q200
R5-R8 = CRCW0402100KFKED: RES, 100 k, 1%, 0.063 W, 0402; Manufacturer: Vishay-Dale; CompType: Resistor; Value: 100k; Res_ohm: 100000; Tolerance_%: 1; Power_W: 0.063; Value2: 0.063W; VDC_V: 50; TempCo: 100 ppm/C; SizeArea_mm2: 0.5; SizeZ_mm: 0.6; EIA_Code: E96; U/M: EA; AEC Category: Q200
U3 = LP8756-Q1RNF: Four-Phase Buck Converter, RNF0026C (VQFN-HR-26); Manufacturer: Texas Instruments; SymbolCreator: Altium; SizeArea_mm2: 18; SizeAreaWB_mm2: 27.5; SizeX_mm: 4; SizeY_mm: 4.5; SizeZ_mm: 0.9; CompType: IC; U/M: EA

## Sheet Memory + IO + CAN Supply.SchDoc
size 431 x 279 mm; Date: Not shown in title block; ApprovedBy: Not shown in title block; CheckedBy: Not shown in title block; Author: Not shown in title block; CompanyName: Not shown in title block; Engineer: Not shown in title block; Organization: Not shown in title block; Address1: Not shown in title block; Address2: Not shown in title block; Address3: Not shown in title block; Address4: Not shown in title block; DocumentNumber: 1; Revision: Use project parameter SCH_Rev; SheetNumber: 4; SheetTotal: 5; PageSetup: Record=PageOptions¦CenterHorizontal=True¦CenterVertical=True¦PrintScale=1.00¦XCorrection=1.00¦YCorrection=1.00¦PrintKind=0¦BorderSize=5000000¦LeftOffset=0¦BottomOffset=0¦Orientation=2¦PaperLength=1000¦PaperWidth=1000¦Scale=100¦PaperSource=15¦PrintQuality=600¦MediaType=1¦DitherType=10¦PaperKind=Letter¦PrintScaleMode=1
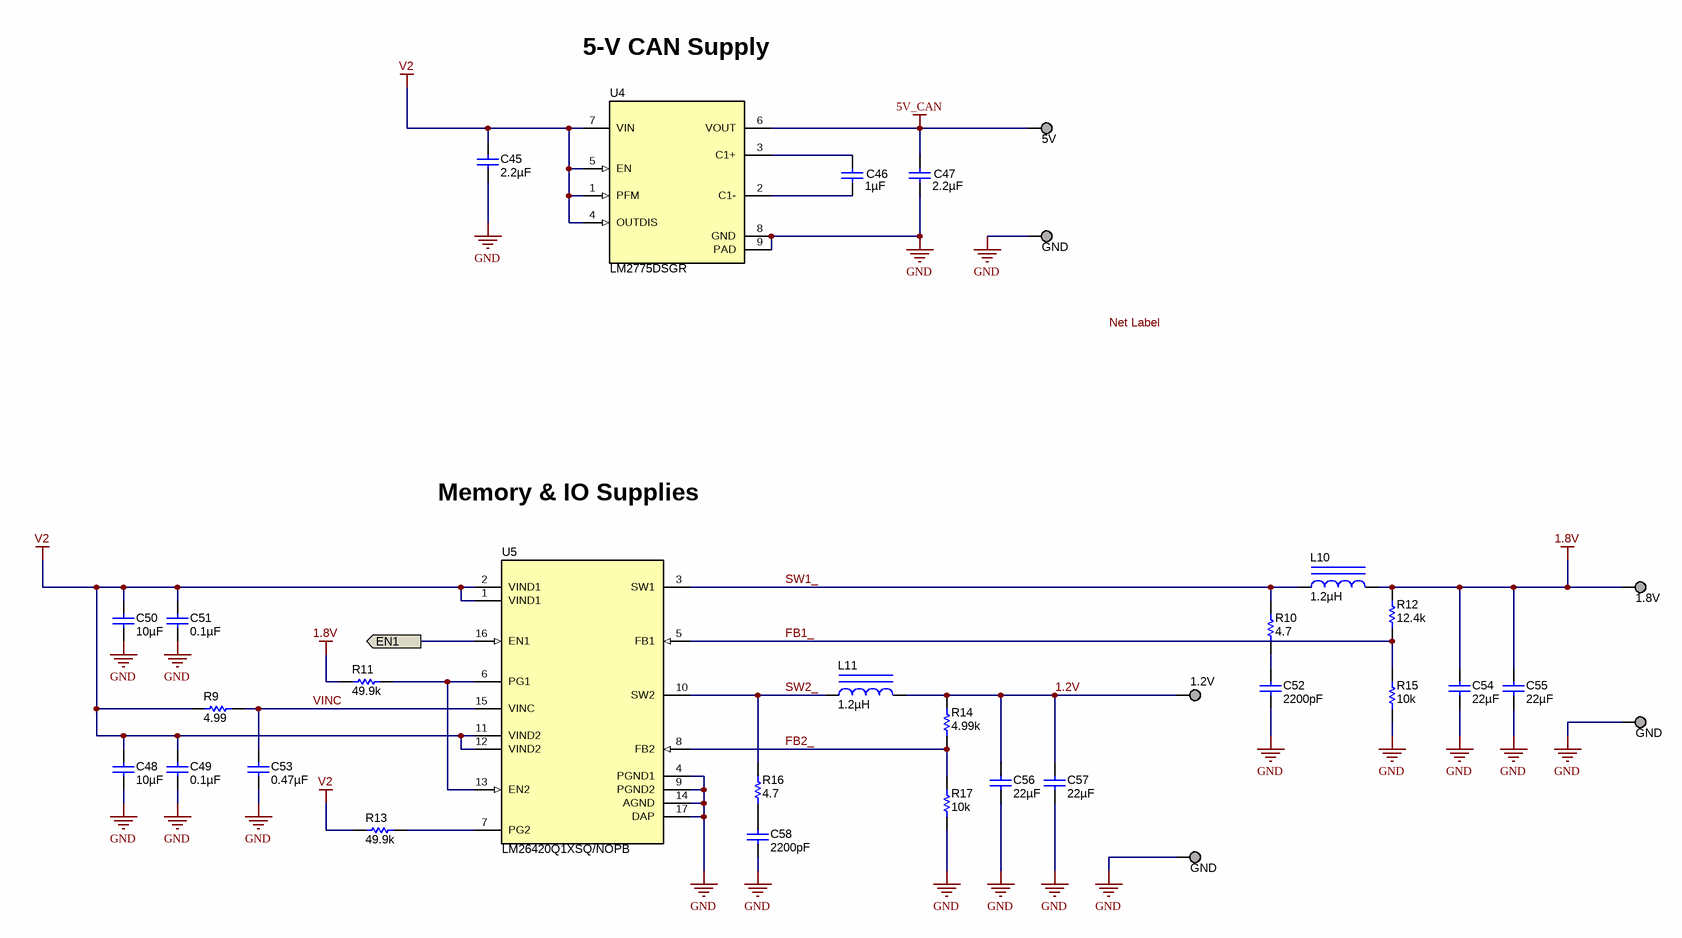
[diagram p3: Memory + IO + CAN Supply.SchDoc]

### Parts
1.2V  1.2V  [Keystone1503-2]  (value not drawn)
1.8V  2010-10-20  [Keystone1503-2]  (value not drawn)
5V  5V  [Keystone1503-2]
C45  ValueDisplayed: 2.2µF  [0603L]  (hidden comment: GRM188R61A225KE34D)
C46  ValueDisplayed: 1µF  [0603]  (hidden comment: C0603C105K8PACTU)
C47  ValueDisplayed: 2.2µF  [0603]  (hidden comment: GRM188R61A225KE34D)
C48  ValueDisplayed: 10µF  [1206_180]  (hidden comment: GCM31CR71A106KA64L)
C49  ValueDisplayed: 0.1µF  [0402L]  (hidden comment: GRM155R71C104JA88D)
C50  ValueDisplayed: 10µF  [1206_180]  (hidden comment: GCM31CR71A106KA64L)
C51  ValueDisplayed: 0.1µF  [0402L]  (hidden comment: GRM155R71C104JA88D)
C52  ValueDisplayed: 2200pF  [0603]  (hidden comment: C0603C222K5RACTU)
C53  ValueDisplayed: 0.47µF  [0603]  (hidden comment: GRM188R71A474KA61D)
C54  ValueDisplayed: 22µF  [1206_180]  (hidden comment: GCM31CR71A226KE02)
C55  ValueDisplayed: 22µF  [1206_180]  (hidden comment: GCM31CR71A226KE02)
C56  ValueDisplayed: 22µF  [1206_180]  (hidden comment: GCM31CR71A226KE02)
C57  ValueDisplayed: 22µF  [1206_180]  (hidden comment: GCM31CR71A226KE02)
C58  ValueDisplayed: 2200pF  [0603]  (hidden comment: C0603C222K5RACTU)
GND2  GND  [Keystone1503-2]
GND3  GND  [Keystone1503-2]
GND4  GND  [Keystone1503-2]
L10  ValueDisplayed: 1.2µH  [XAL5030]  (hidden comment: XAL5030-122MEB)
L11  ValueDisplayed: 1.2µH  [XAL5030]  (hidden comment: XAL5030-122MEB)
R9  value 4.99  [0805L]  (hidden comment: RC0805FR-074R99L)
R10  value 4.7  [0805_HV]  (hidden comment: CRCW08054R70JNEA)
R11  value 49.9k  [0603L]  (hidden comment: CRCW060349K9FKEA)
R12  value 12.4k  [0603L]  (hidden comment: CRCW060312K4FKEA)
R13  value 49.9k  [0603L]  (hidden comment: CRCW060349K9FKEA)
R14  ValueDisplayed: 4.99k  [0603L]  (hidden comment: CRCW06034K99FKEA)
R15  value 10k  [0603]  (hidden comment: CRCW060310K0JNEA)
R16  value 4.7  [0805_HV]  (hidden comment: CRCW08054R70JNEA)
R17  value 10k  [0603]  (hidden comment: CRCW060310K0JNEA)
U4  LM2775DSGR  [DSG0008A]
U5  LM26420Q1XSQ/NOPB  [RUM0016A]

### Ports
EN1 (out)

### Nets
1.8V: 1.8V.1 C54.1 C55.1 L10.2 R11.1 R12.2
5V_CAN: 5V.1 C47.1 U4.6(VOUT)
GND: C45.2 C47.2 C48.2 C49.1 C50.2 C51.1 C52.2 C53.2 C54.2 C55.2 C56.2 C57.2 C58.2 GND2.1 GND3.1 GND4.1 R15.1 R17.1 U4.8(GND) U4.9(PAD) U5.4(PGND1) U5.9(PGND2) U5.14(AGND) U5.17(DAP)
V2: C45.1 C48.1 C49.2 C50.1 C51.2 R9.1 R13.1 U4.1(PFM) U4.4(OUTDIS) U4.5(EN) U4.7(VIN) U5.1(VIND1) U5.2(VIND1) U5.11(VIND2) U5.12(VIND2)
1.2V: 1.2V.1 C56.1 C57.1 L11.2 R14.2
FB1_: R12.1 R15.2 U5.5(FB1)
FB2_: R14.1 R17.2 U5.8(FB2)
SW1_: L10.1 R10.1 U5.3(SW1)
SW2_: L11.1 R16.2 U5.10(SW2)
VINC: C53.1 R9.2 U5.15(VINC)
NetC46_1: C46.1 U4.3(C1+)
NetC46_2: C46.2 U4.2(C1-)
NetC52_1: C52.1 R10.2
NetC58_1: C58.1 R16.1
NetR11_2: R11.2 U5.6(PG1) U5.13(EN2)
NetR13_2: R13.2 U5.7(PG2)
NetRPG_1: U5.16(EN1) ; port EN1

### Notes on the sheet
- 5-V CAN Supply
- Memory & IO Supplies
- Labels drawn without touching a wire or pin: Net Label

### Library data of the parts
1.2V 1.8V 5V GND2-GND4 = 1503-2: as 0.9V on sheet Core-Voltage Supply
C45 = GRM188R61A225KE34D: CAP, CERM, 2.2 µF, 10 V, +/- 10%, X5R, 0603; Manufacturer: MuRata; Polarized: N; CompType: Capacitor; Value: 2.2uF; U/M: EA; Cap_F: 0.0000022; Tolerance_%: 10; Value1: Unknown; Value2: 10V; TaMin_C: -55; TaMax_C: 85; Cap_Case: 0603
C46 = C0603C105K8PACTU: CAP, CERM, 1 µF, 10 V, +/- 10%, X5R, 0603; Manufacturer: Kemet; Polarized: N; CompType: Capacitor; Value: 1uF; U/M: EA; Cap_F: 0.000001; Tolerance_%: 10; Value1: Unknown; Value2: 10V; TaMin_C: -55; TaMax_C: 85
C47 = GRM188R61A225KE34D: CAP, CERM, 2.2 µF, 10 V, +/- 10%, X5R, 0603; Manufacturer: MuRata; Polarized: N; CompType: Capacitor; Value: 2.2uF; U/M: EA; Cap_F: 0.0000022; Tolerance_%: 10; Value1: Unknown; Value2: 10V; TaMin_C: -55; TaMax_C: 85
C48 C50 = GCM31CR71A106KA64L: as C32 on sheet Core-Voltage Supply
C49 C51 = GRM155R71C104JA88D: as C20 on sheet Core-Voltage Supply
C52 C58 = C0603C222K5RACTU: CAP, CERM, 2200pF, 50V, +/-10%, X7R, 0603; Manufacturer: Kemet; Polarized: N; CompType: Capacitor; U/M: EA; Cap_F: 0.0000000022; Tolerance_%: 10; Value1: Unknown; VDC_V: 50; TaMin_C: -55; TaMax_C: 125
C53 = GRM188R71A474KA61D: CAP, CERM, 0.47uF, 10V, +/-10%, X7R, 0603; Manufacturer: MuRata; Polarized: N; CompType: Capacitor; U/M: EA; Cap_F: 0.00000047; Tolerance_%: 10; Value1: Unknown; TaMin_C: -55; TaMax_C: 125
C54-C57 = GCM31CR71A226KE02: CAP, CERM, 22 µF, 10 V, +/- 10%, X7R, AEC-Q200 Grade 1, 1206; Manufacturer: MuRata; Polarized: N; CompType: Capacitor; Value: 22uF; U/M: EA; Cap_F: 0.000022; Tolerance_%: 10; Value1: Unknown; Value2: 10V; TaMin_C: -55; TaMax_C: 125; Cap_Case: 1206; SizeArea_mm2: 5.12; SizeAreaWB_mm2: 10.92; SizeX_mm: 3.2; SizeY_mm: 1.6; SizeZ_mm: 1.8; AEC Category: Q200; AEC Qualified: Y; AEC Grade: 1
L10 L11 = XAL5030-122MEB: Inductor, Shielded, Composite, 1.2 µH, 11.1 A, 0.01 ohm, SMD; Manufacturer: Coilcraft; Value: 1.2uH; Ind_H: 1.2E-6; Imax_A: 11.1; Irms: 11.1A @ 40C rise; Isat: 12.5A @ 30% inductance drop; DCR_ohm: 0.01; Value2: 11.1A; SizeAreaWB_mm2: 54.4544; SizeArea_mm2: 28.9344; SizeX_mm: 5.28; SizeY_mm: 5.48; SizeZ_mm: 3.1; AEC Category: Q200
R9 = RC0805FR-074R99L: RES, 4.99 ohm, 1%, 0.125W, 0805; Manufacturer: Yageo America; CompType: Resistor; Value_Code: 4R99; Tolerance_%: 1; Power_W: 0.125; VDC_V: 150; TempCo: 200 ppm/C; EIA_Code: E96; U/M: EA
R10 R16 = CRCW08054R70JNEA: RES, 4.7 ohm, 5%, 0.125W, 0805; Manufacturer: Vishay-Dale; CompType: Resistor; Value_Code: 4R70; Tolerance_%: 5; Power_W: 0.125; VDC_V: 150; TempCo: 200 ppm/C; EIA_Code: E24; U/M: EA
R11 R13 = CRCW060349K9FKEA: RES, 49.9k ohm, 1%, 0.1W, 0603; Manufacturer: Vishay-Dale; CompType: Resistor; Res_ohm: 49900; Value_Code: 49k9; Tolerance_%: 1; Power_W: 0.1; VDC_V: 75; TempCo: 100 ppm/C; EIA_Code: E96; U/M: EA
R12 = CRCW060312K4FKEA: RES, 12.4k ohm, 1%, 0.1W, 0603; Manufacturer: Vishay-Dale; CompType: Resistor; Res_ohm: 12400; Value_Code: 12k4; Tolerance_%: 1; Power_W: 0.1; VDC_V: 75; TempCo: 100 ppm/C; EIA_Code: E96; U/M: EA
R14 = CRCW06034K99FKEA: RES, 4.99 k, 1%, 0.1 W, 0603; Manufacturer: Vishay-Dale; CompType: Resistor; Value: 4.99k; Res_ohm: 4990; Value_Code: 4k99; Tolerance_%: 1; Power_W: 0.1; Value2: 0.1W; VDC_V: 75; TempCo: 100 ppm/C; EIA_Code: E96; U/M: EA; SizeArea_mm2: 1.28; SizeX_mm: 1.6; SizeY_mm: 0.8; AEC Category: Q200
R15 R17 = CRCW060310K0JNEA: RES, 10k ohm, 5%, 0.1W, 0603; Manufacturer: Vishay-Dale; CompType: Resistor; Res_ohm: 10000; Value_Code: 10k0; Tolerance_%: 5; Power_W: 0.1; VDC_V: 75; TempCo: 200 ppm/C; EIA_Code: E24; U/M: EA
U4 = LM2775DSGR: Switched Capacitor 5 V Boost Converter, DSG0008A (WSON-8); Alternate PartNumber: LM2775DSGT; Manufacturer: Texas Instruments; SymbolCreator: Altium; SizeArea_mm2: 4; SizeAreaWB_mm2: 9; SizeX_mm: 2; SizeZ_mm: 0.8; CompType: IC; U/M: EA
U5 = LM26420Q1XSQ/NOPB: Dual 2-A, High Frequency Synchronous Buck Regulator, RUM0016A (WQFN-16); Manufacturer: Texas Instruments; SymbolCreator: Altium; SizeArea_mm2: 16; SizeAreaWB_mm2: 25; SizeX_mm: 4; SizeZ_mm: 0.8; CompType: IC; U/M: EA

## Sheet TIDA-01492_EVM_Hardware.SchDoc
size 431 x 279 mm; Date: Not shown in title block; ApprovedBy: Not shown in title block; CheckedBy: Not shown in title block; Author: Not shown in title block; CompanyName: Not shown in title block; Engineer: Not shown in title block; Organization: Not shown in title block; Address1: Not shown in title block; Address2: Not shown in title block; Address3: Not shown in title block; Address4: Not shown in title block; DocumentNumber: 1; Revision: Use project parameter SCH_Rev; SheetNumber: 5; SheetTotal: 5; PageSetup: Record=PageOptions¦CenterHorizontal=True¦CenterVertical=True¦PrintScale=1.00¦XCorrection=1.00¦YCorrection=1.00¦PrintKind=0¦BorderSize=5000000¦LeftOffset=0¦BottomOffset=0¦Orientation=2¦PaperLength=1000¦PaperWidth=1000¦Scale=100¦PaperSource=15¦PrintQuality=600¦MediaType=1¦DitherType=10¦PaperKind=Letter¦PrintScaleMode=1
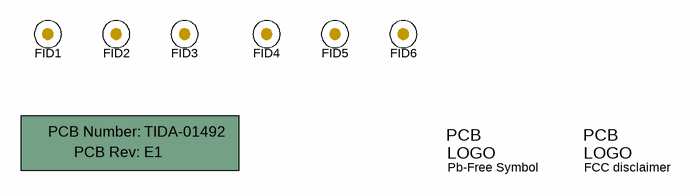
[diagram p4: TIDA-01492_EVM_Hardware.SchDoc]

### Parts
!PCB1  TIDA-01492  (value not drawn)  (mechanical)
FID1  Fiducial  [Fiducial10-20]  (value not drawn)
FID2  Fiducial  [Fiducial10-20]  (value not drawn)
FID3  Fiducial  [Fiducial10-20]  (value not drawn)
FID4  Fiducial  [Fiducial10-20]  (value not drawn)
FID5  Fiducial  [Fiducial10-20]  (value not drawn)
FID6  Fiducial  [Fiducial10-20]  (value not drawn)
Logo2  Pb-Free Symbol  [Pb-Free_Overlay_Small]  (no BOM)
Logo3  FCC disclaimer  [FCC_disclaimer]  (no BOM)

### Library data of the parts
!PCB1 = PCB: Printed Circuit Board; Manufacturer: Any; SymbolCreator: a0412235
FID1-FID6 = Fiducial: Fiducial mark.  There is nothing to buy or mount.; SymbolCreator: codlsc
Logo2 = Pb-Free: SymbolCreator: a0412235
Logo3 = FCC_disclaimer: SymbolCreator: codlsc

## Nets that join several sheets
GND: Main Supply + Smart Diode (38 pins), Core-Voltage Supply (51 pins), Memory + IO + CAN Supply (24 pins)
V2: Main Supply + Smart Diode (11 pins), Core-Voltage Supply (14 pins), Memory + IO + CAN Supply (15 pins)
NetRPG_1: Main Supply + Smart Diode (RPG.1 U2.16), Core-Voltage Supply (U3.2 U3.5 U3.7 U3.15), Memory + IO + CAN Supply (U5.16)

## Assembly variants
TIDA-01492 Web Ready: not fitted Logo1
